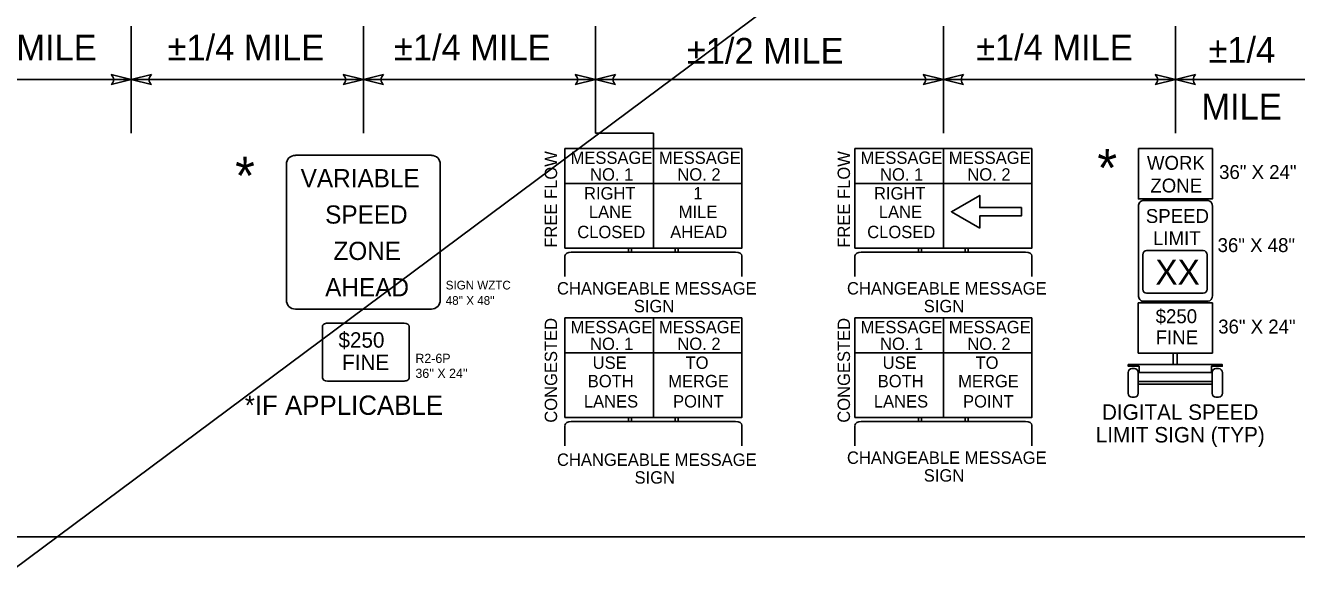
# Model space of a CAD drawing. Extents: x 1379436 to 1387057, y 792703 to 795604.
# Drawn here: x 1381631 to 1382289, y 794247 to 794533 of the extents above; entities that cross this region are included whole.
import ezdxf

# ---------------------------------------------------------------- set-up
doc = ezdxf.new("R2010")
doc.units = 0
for name, color, linetype in [('Default', 7, 'Continuous'), ('DEV CMS TEXT CELL', 7, 'Continuous'), ('DEV LINE TERMINATOR TYPE 3 CELL', 7, 'Continuous'), ('Gray Area Fill Shapes', 7, 'Continuous'), ('Old_Level_2', 7, 'Continuous'), ('RS R5-1A CELL', 7, 'Continuous'), ('TCP Linework', 7, 'Continuous'), ('Text', 7, 'Continuous'), ('WS W24-1cP24 CELL', 7, 'Continuous')]:
    doc.layers.add(name, color=color, linetype=linetype)

msp = doc.modelspace()

# ---------------------------------------------------------------- linework, layer by layer
at = {"layer": 'Default'}
for p, q in [((1379547.85, 792703.35), (1383441.11, 795604.31)), ((1381685.89, 794532.28), (1381685.89, 794476.77)), ((1381805.89, 794532.28), (1381805.89, 794476.77)), ((1381925.89, 794532.28), (1381925.89, 794476.77)), ((1382105.89, 794532.28), (1382105.89, 794476.77)), ((1382225.89, 794532.28), (1382225.89, 794476.77)), ((1380845.89, 794504.52), (1382495.75, 794504.52)), ((1381925.89, 794476.77), (1381925.89, 794504.52)), ((1381925.89, 794476.77), (1381955.91, 794476.77)), ((1381955.91, 794468.84), (1381955.91, 794476.77)), ((1380316.98, 794267.83), (1382566.98, 794267.84))]:
    msp.add_line(p, q, dxfattribs=at)
for points in [[(1382206.77, 794392.85), (1382206.77, 794438.89)], [(1382209, 794441.93), (1382242.78, 794441.93)], [(1382245.01, 794438.89), (1382245.01, 794392.85)], [(1382242.78, 794389.81), (1382209, 794389.81)]]:
    msp.add_lwpolyline(points, dxfattribs=at)
for centre, major_axis, start_param, end_param in [((1382209, 794438.89), (0, 3.04), 6.282958, 7.853982), ((1382242.78, 794438.89), (0, 3.04), 4.712389, 6.283185), ((1382209, 794392.85), (0, 3.04), 1.570796, 3.141593), ((1382242.78, 794392.85), (0, -3.04), 0, 1.570796)]:
    msp.add_ellipse(centre, major_axis=major_axis, ratio=0.733811, start_param=start_param, end_param=end_param, dxfattribs=at)
at = {"layer": 'DEV CMS TEXT CELL'}
for p, q in [((1381910.16, 794468.84), (1382001.67, 794468.84)), ((1381910.16, 794417.37), (1381910.16, 794468.84)), ((1381955.91, 794417.37), (1381955.91, 794468.84)), ((1381955.91, 794417.37), (1381955.91, 794468.84)), ((1382001.67, 794417.37), (1382001.67, 794468.84)), ((1382060.13, 794468.84), (1382151.65, 794468.84)), ((1382060.13, 794417.37), (1382060.13, 794468.84)), ((1382105.89, 794417.37), (1382105.89, 794468.84)), ((1382105.89, 794417.37), (1382105.89, 794468.84)), ((1382151.65, 794417.37), (1382151.65, 794468.84)), ((1381910.16, 794450.73), (1381955.91, 794450.73)), ((1382001.67, 794450.73), (1381955.91, 794450.73)), ((1382060.13, 794450.73), (1382105.89, 794450.73)), ((1382151.65, 794450.73), (1382105.89, 794450.73)), ((1382001.67, 794417.37), (1381910.16, 794417.37)), ((1381943.05, 794417.37), (1381943.05, 794415.24)), ((1381944.63, 794417.37), (1381944.63, 794415.24)), ((1381967.2, 794417.37), (1381967.2, 794415.24)), ((1381968.78, 794417.37), (1381968.78, 794415.24)), ((1382151.65, 794417.37), (1382060.13, 794417.37)), ((1382093.02, 794417.37), (1382093.02, 794415.24)), ((1382094.61, 794417.37), (1382094.61, 794415.24)), ((1382117.17, 794417.37), (1382117.17, 794415.24)), ((1382118.75, 794417.37), (1382118.75, 794415.24)), ((1381910.16, 794413.24), (1381910.16, 794402.62)), ((1381913.36, 794415.24), (1381998.45, 794415.24)), ((1382001.69, 794413.25), (1382001.69, 794402.63)), ((1382060.13, 794413.24), (1382060.13, 794402.62)), ((1382063.34, 794415.24), (1382148.42, 794415.24)), ((1382151.66, 794413.25), (1382151.66, 794402.63)), ((1381910.16, 794381.18), (1382001.67, 794381.18)), ((1381910.16, 794329.7), (1381910.16, 794381.18)), ((1381955.91, 794329.7), (1381955.91, 794381.18)), ((1381955.91, 794329.7), (1381955.91, 794381.18)), ((1382001.67, 794329.7), (1382001.67, 794381.18)), ((1382060.13, 794381.18), (1382151.65, 794381.18)), ((1382060.13, 794329.7), (1382060.13, 794381.18)), ((1382105.89, 794329.7), (1382105.89, 794381.18)), ((1382105.89, 794329.7), (1382105.89, 794381.18)), ((1382151.65, 794329.7), (1382151.65, 794381.18)), ((1381910.16, 794363.07), (1381955.91, 794363.07)), ((1382001.67, 794363.07), (1381955.91, 794363.07)), ((1382060.13, 794363.07), (1382105.89, 794363.07)), ((1382151.65, 794363.07), (1382105.89, 794363.07)), ((1382001.67, 794329.7), (1381910.16, 794329.7)), ((1381910.16, 794325.57), (1381910.16, 794314.95)), ((1381913.36, 794327.57), (1381998.45, 794327.57)), ((1381943.05, 794329.7), (1381943.05, 794327.57)), ((1381944.63, 794329.7), (1381944.63, 794327.57)), ((1381967.2, 794329.7), (1381967.2, 794327.57)), ((1381968.78, 794329.7), (1381968.78, 794327.57)), ((1382001.69, 794325.59), (1382001.69, 794314.97)), ((1382151.65, 794329.7), (1382060.13, 794329.7)), ((1382060.13, 794325.57), (1382060.13, 794314.95)), ((1382063.34, 794327.57), (1382148.42, 794327.57)), ((1382093.02, 794329.7), (1382093.02, 794327.57)), ((1382094.61, 794329.7), (1382094.61, 794327.57)), ((1382117.17, 794329.7), (1382117.17, 794327.57)), ((1382118.75, 794329.7), (1382118.75, 794327.57)), ((1382151.66, 794325.59), (1382151.66, 794314.97))]:
    msp.add_line(p, q, dxfattribs=at)
msp.add_lwpolyline([(1382124.71, 794427.67), (1382110.03, 794436.15), (1382124.71, 794444.63), (1382124.71, 794438.28), (1382146.22, 794438.28), (1382146.22, 794434.02), (1382124.71, 794434.02)], close=True, dxfattribs=at)
for centre, major_axis, start_param, end_param in [((1381913.38, 794413.25), (-3.24, 0), 4.712389, 6.283185), ((1381998.45, 794413.25), (3.24, 0), 0, 1.570796), ((1382063.35, 794413.25), (-3.24, 0), 4.712389, 6.283185), ((1382148.42, 794413.25), (3.24, 0), 0, 1.570796), ((1381913.38, 794325.59), (-3.24, 0), 4.712389, 6.283185), ((1381998.45, 794325.59), (3.24, 0), 0, 1.570796), ((1382063.35, 794325.59), (-3.24, 0), 4.712389, 6.283185), ((1382148.42, 794325.59), (3.24, 0), 0, 1.570796)]:
    msp.add_ellipse(centre, major_axis=major_axis, ratio=0.606795, start_param=start_param, end_param=end_param, dxfattribs=at)
at = {"layer": 'DEV LINE TERMINATOR TYPE 3 CELL'}
for points in [[(1381675.49, 794501.92), (1381685.89, 794504.52), (1381675.49, 794507.12)], [(1381675.49, 794501.92), (1381685.89, 794504.52), (1381675.49, 794507.12)], [(1381696.28, 794501.92), (1381685.89, 794504.52), (1381696.28, 794507.12)], [(1381696.28, 794501.92), (1381685.89, 794504.52), (1381696.28, 794507.12)], [(1381795.49, 794501.92), (1381805.89, 794504.52), (1381795.49, 794507.12)], [(1381795.49, 794501.92), (1381805.89, 794504.52), (1381795.49, 794507.12)], [(1381816.28, 794501.92), (1381805.89, 794504.52), (1381816.28, 794507.12)], [(1381816.28, 794501.92), (1381805.89, 794504.52), (1381816.28, 794507.12)], [(1381915.49, 794501.92), (1381925.89, 794504.52), (1381915.49, 794507.12)], [(1381915.49, 794501.92), (1381925.89, 794504.52), (1381915.49, 794507.12)], [(1381936.28, 794501.92), (1381925.89, 794504.52), (1381936.28, 794507.12)], [(1381936.28, 794501.92), (1381925.89, 794504.52), (1381936.28, 794507.12)], [(1382095.49, 794501.92), (1382105.89, 794504.52), (1382095.49, 794507.12)], [(1382095.49, 794501.92), (1382105.89, 794504.52), (1382095.49, 794507.12)], [(1382116.28, 794501.92), (1382105.89, 794504.52), (1382116.28, 794507.12)], [(1382116.28, 794501.92), (1382105.89, 794504.52), (1382116.28, 794507.12)], [(1382215.49, 794501.92), (1382225.89, 794504.52), (1382215.49, 794507.12)], [(1382215.49, 794501.92), (1382225.89, 794504.52), (1382215.49, 794507.12)], [(1382236.28, 794501.92), (1382225.89, 794504.52), (1382236.28, 794507.12)], [(1382236.28, 794501.92), (1382225.89, 794504.52), (1382236.28, 794507.12)]]:
    msp.add_lwpolyline(points, dxfattribs=at)
for centre, start, end in [((1381673.21, 794504.52), 311.32644, 48.67357), ((1381673.21, 794504.52), 311.32644, 48.67357), ((1381698.57, 794504.52), 131.32643, 228.67356), ((1381698.57, 794504.52), 131.32643, 228.67356), ((1381793.21, 794504.52), 311.32644, 48.67357), ((1381793.21, 794504.52), 311.32644, 48.67357), ((1381818.57, 794504.52), 131.32643, 228.67356), ((1381818.57, 794504.52), 131.32643, 228.67356), ((1381913.21, 794504.52), 311.32644, 48.67357), ((1381913.21, 794504.52), 311.32644, 48.67357), ((1381938.57, 794504.52), 131.32643, 228.67356), ((1381938.57, 794504.52), 131.32643, 228.67356), ((1382093.21, 794504.52), 311.32644, 48.67357), ((1382093.21, 794504.52), 311.32644, 48.67357), ((1382118.57, 794504.52), 131.32643, 228.67356), ((1382118.57, 794504.52), 131.32643, 228.67356), ((1382213.21, 794504.52), 311.32644, 48.67357), ((1382213.21, 794504.52), 311.32644, 48.67357), ((1382238.57, 794504.52), 131.32643, 228.67356), ((1382238.57, 794504.52), 131.32643, 228.67356)]:
    msp.add_arc(centre, 3.46, start, end, dxfattribs=at)
at = {"layer": 'Gray Area Fill Shapes'}
for p, q in [((1382209.03, 794413.85), (1382209.03, 794396.09)), ((1382240.3, 794416.01), (1382211.01, 794416.01)), ((1382242.28, 794396.09), (1382242.28, 794413.85)), ((1382211.01, 794393.93), (1382240.3, 794393.93))]:
    msp.add_line(p, q, dxfattribs=at)
for points in [[(1381955.91, 794450.73), (1381910.16, 794450.73), (1381910.16, 794417.37), (1381955.91, 794417.37)], [(1381955.91, 794450.73), (1382001.67, 794450.73), (1382001.67, 794417.37), (1381955.91, 794417.37)], [(1382105.89, 794450.73), (1382060.13, 794450.73), (1382060.13, 794417.37), (1382105.89, 794417.37)], [(1382105.89, 794450.73), (1382151.65, 794450.73), (1382151.65, 794417.37), (1382105.89, 794417.37)], [(1381955.91, 794363.07), (1381910.16, 794363.07), (1381910.16, 794329.7), (1381955.91, 794329.7)], [(1381955.91, 794363.07), (1382001.67, 794363.07), (1382001.67, 794329.7), (1381955.91, 794329.7)], [(1382105.89, 794363.07), (1382060.13, 794363.07), (1382060.13, 794329.7), (1382105.89, 794329.7)], [(1382105.89, 794363.07), (1382151.65, 794363.07), (1382151.65, 794329.7), (1382105.89, 794329.7)]]:
    msp.add_lwpolyline(points, close=True, dxfattribs=at)
for centre, major_axis, start_param, end_param in [((1382211.01, 794413.85), (0, 2.16), 0, 1.570796), ((1382240.3, 794413.85), (0, 2.16), 4.712389, 6.283185), ((1382211.01, 794396.09), (0, -2.16), 4.712389, 6.283185), ((1382240.3, 794396.09), (0, -2.16), 0, 1.570796)]:
    msp.add_ellipse(centre, major_axis=major_axis, ratio=0.917264, start_param=start_param, end_param=end_param, dxfattribs=at)
at = {"layer": 'Old_Level_2'}
for points in [[(1382206.74, 794468.84), (1382245.04, 794468.84), (1382245.04, 794442.79), (1382206.74, 794442.79)], [(1382206.72, 794388.92), (1382245.01, 794388.92), (1382245.01, 794362.98), (1382206.72, 794362.98)]]:
    msp.add_lwpolyline(points, close=True, dxfattribs=at)
at = {"layer": 'RS R5-1A CELL'}
msp.add_line((1381827.02, 794348.5), (1381787.34, 794348.5), dxfattribs=at)
for points in [[(1381787.34, 794378.45), (1381827.02, 794378.45)], [(1381787.34, 794378.45), (1381807.18, 794378.45)], [(1381807.18, 794378.45), (1381827.02, 794378.45)], [(1381784.72, 794350.25), (1381784.72, 794376.7)], [(1381784.72, 794350.25), (1381784.72, 794376.7)], [(1381829.64, 794376.7), (1381829.64, 794350.25)], [(1381829.64, 794376.7), (1381829.64, 794350.25)], [(1381807.18, 794348.5), (1381787.34, 794348.5)], [(1381827.02, 794348.5), (1381807.18, 794348.5)]]:
    msp.add_lwpolyline(points, dxfattribs=at)
for centre, major_axis, start_param, end_param in [((1381787.34, 794376.7), (-2.62, 0), 4.712162, 6.283185), ((1381787.34, 794376.7), (-2.62, 0), 4.712162, 6.283185), ((1381827.02, 794376.7), (2.62, 0), 0, 1.570796), ((1381827.02, 794376.7), (2.62, 0), 0, 1.570796), ((1381787.34, 794350.25), (-2.62, 0), 0, 1.570796), ((1381787.34, 794350.25), (-2.62, 0), 0, 1.570796), ((1381827.02, 794350.25), (-2.62, 0), 1.570796, 3.141593), ((1381827.02, 794350.25), (-2.62, 0), 1.570796, 3.141593)]:
    msp.add_ellipse(centre, major_axis=major_axis, ratio=0.666667, start_param=start_param, end_param=end_param, dxfattribs=at)
at = {"layer": 'TCP Linework'}
for points in [[(1382224.73, 794357), (1382226.86, 794357), (1382226.86, 794362.98), (1382224.73, 794362.98)], [(1382206.67, 794346.92), (1382244.93, 794346.92), (1382244.93, 794348.19), (1382206.67, 794348.19)]]:
    msp.add_lwpolyline(points, close=True, dxfattribs=at)
for points in [[(1382201.43, 794342.23), (1382201.43, 794352.88)], [(1382244.91, 794357), (1382206.68, 794357), (1382201.5, 794356.99), (1382201.5, 794356.15), (1382207.07, 794356.16), (1382207.07, 794352.9), (1382244.51, 794352.93), (1382244.51, 794356.15)], [(1382203.34, 794354.96), (1382204.77, 794354.96)], [(1382206.67, 794352.88), (1382206.67, 794342.23)], [(1382206.68, 794357), (1382244.91, 794357), (1382250.09, 794356.99), (1382250.09, 794356.15), (1382244.51, 794356.17), (1382244.51, 794352.87), (1382207.07, 794352.9), (1382207.07, 794356.15)], [(1382244.93, 794342.23), (1382244.93, 794352.88)], [(1382246.83, 794354.96), (1382248.27, 794354.96)], [(1382250.17, 794352.88), (1382250.17, 794342.23)], [(1382204.77, 794340.15), (1382203.34, 794340.15)], [(1382248.27, 794340.15), (1382246.83, 794340.15)]]:
    msp.add_lwpolyline(points, dxfattribs=at)
for centre, major_axis, start_param, end_param in [((1382203.34, 794352.88), (0, 2.08), 0, 1.570796), ((1382204.77, 794352.88), (0, 2.08), 4.712389, 6.283185), ((1382246.83, 794352.88), (0, -2.08), 3.141593, 4.712389), ((1382248.27, 794352.88), (0, 2.08), 4.712389, 6.283185), ((1382203.34, 794342.23), (0, -2.08), 4.712389, 6.283185), ((1382204.77, 794342.23), (0, -2.08), 0, 1.570796), ((1382246.83, 794342.23), (0, -2.08), 4.712389, 6.283185), ((1382248.27, 794342.23), (0, 2.08), 3.141593, 4.712389)]:
    msp.add_ellipse(centre, major_axis=major_axis, ratio=0.917264, start_param=start_param, end_param=end_param, dxfattribs=at)
at = {"layer": 'WS W24-1cP24 CELL'}
msp.add_line((1381845.7, 794460.7), (1381845.7, 794390.39), dxfattribs=at)
for points in [[(1381770.72, 794465.34), (1381841.06, 794465.34)], [(1381766.07, 794390.39), (1381766.07, 794460.7)], [(1381805.89, 794385.75), (1381770.72, 794385.75)], [(1381841.06, 794385.75), (1381805.89, 794385.75)]]:
    msp.add_lwpolyline(points, dxfattribs=at)
for centre, major_axis, start_param, end_param in [((1381770.72, 794460.7), (-4.64, 0), 4.712162, 6.283185), ((1381841.06, 794460.7), (4.64, 0), 0, 1.570796), ((1381770.72, 794390.39), (-4.64, 0), 0, 1.570796), ((1381841.06, 794390.39), (-4.64, 0), 1.570796, 3.141593)]:
    msp.add_ellipse(centre, major_axis=major_axis, ratio=0.999525, start_param=start_param, end_param=end_param, dxfattribs=at)

# ---------------------------------------------------------------- texts
at = {"layer": 'Default'}
for s, height, p in [('*', 19.68, (1381739.56, 794444.97)), ('*', 19.68, (1382185.49, 794449.01)), ('36" X 24"', 7.203, (1382248.49, 794453.1)), ('36" X 48"', 7.203, (1382247.72, 794415.26)), ('36" X 24"', 7.203, (1382248.02, 794373.11)), ('*IF APPLICABLE', 10, (1381744.57, 794331.01))]:
    msp.add_text(s, height=height, dxfattribs=at).set_placement(p)
at = {"layer": 'DEV CMS TEXT CELL'}
for s, rotation, p in [('FREE FLOW', 90, (1381906.1, 794417.55)), ('MESSAGE', 360, (1381958.72, 794460.92)), ('FREE FLOW', 90, (1382057.6, 794417.55)), ('MESSAGE', 360, (1382108.69, 794460.92)), ('NO. 2', 360, (1381968.29, 794452.25)), ('NO. 2', 360, (1382118.27, 794452.25)), ('CONGESTED', 90, (1381906.1, 794326.94)), ('MESSAGE', 360, (1381958.72, 794373.25)), ('CONGESTED', 90, (1382057.6, 794326.94)), ('MESSAGE', 360, (1382108.69, 794373.25)), ('NO. 2', 360, (1381968.29, 794364.58)), ('NO. 2', 360, (1382118.27, 794364.58))]:
    msp.add_text(s, height=6.403, rotation=rotation, dxfattribs=at).set_placement(p)
for s, height, p in [('MESSAGE', 6.403, (1381913.05, 794460.92)), ('MESSAGE', 6.403, (1382063.02, 794460.92)), ('NO. 1', 6.403, (1381923.16, 794452.25)), ('NO. 1', 6.403, (1382073.14, 794452.25)), ('RIGHT', 6.403, (1381920.03, 794442.49)), ('1', 6.4, (1381976.53, 794442.49)), ('RIGHT', 6.403, (1382070.01, 794442.49)), ('LANE', 6.403, (1381922.53, 794432.95)), ('MILE', 6.403, (1381969.02, 794432.95)), ('LANE', 6.403, (1382072.5, 794432.95)), ('CLOSED', 6.403, (1381916.53, 794422.47)), ('AHEAD', 6.403, (1381964.61, 794422.47)), ('CLOSED', 6.403, (1382066.5, 794422.47)), ('CHANGEABLE MESSAGE', 6.4025, (1381906.04, 794393.3)), ('CHANGEABLE MESSAGE', 6.4025, (1382056.02, 794393.3)), ('SIGN', 6.403, (1381945.78, 794384.11)), ('SIGN', 6.403, (1382095.75, 794384.11)), ('MESSAGE', 6.403, (1381913.05, 794373.25)), ('MESSAGE', 6.403, (1382063.02, 794373.25)), ('NO. 1', 6.403, (1381923.16, 794364.58)), ('NO. 1', 6.403, (1382073.14, 794364.58)), ('USE', 6.403, (1381924.5, 794354.82)), ('TO', 6.403, (1381972.54, 794354.82)), ('USE', 6.403, (1382074.47, 794354.82)), ('TO', 6.403, (1382122.52, 794354.82)), ('BOTH', 6.403, (1381921.96, 794345.28)), ('MERGE', 6.403, (1381963.54, 794345.28)), ('BOTH', 6.403, (1382071.93, 794345.28)), ('MERGE', 6.403, (1382113.52, 794345.28)), ('LANES', 6.403, (1381919.94, 794334.8)), ('POINT', 6.403, (1381966.07, 794334.8)), ('LANES', 6.403, (1382069.92, 794334.8)), ('POINT', 6.403, (1382116.05, 794334.8)), ('CHANGEABLE MESSAGE', 6.4025, (1381906.04, 794304.6)), ('CHANGEABLE MESSAGE', 6.4025, (1382056.02, 794305.64)), ('SIGN', 6.403, (1381946.16, 794295.41)), ('SIGN', 6.403, (1382095.75, 794296.45))]:
    msp.add_text(s, height=height, dxfattribs=at).set_placement(p)
at = {"layer": 'RS R5-1A CELL'}
for s, height, p in [('$250', 7.986, (1381793.04, 794365.77)), ('FINE', 7.986, (1381794.92, 794354.15)), ('R2-6P', 4.792, (1381832.83, 794357.85)), ("36'' X 24''", 4.7916, (1381832.83, 794350.11))]:
    msp.add_text(s, height=height, dxfattribs=at).set_placement(p)
at = {"layer": 'Text'}
for s, height, p in [('±1/4 MILE', 13.31, (1381586.96, 794514.45)), ('±1/4 MILE', 13.31, (1381704.63, 794514.45)), ('±1/4 MILE', 13.31, (1381821.75, 794514.45)), ('±1/2 MILE', 13.31, (1381973.23, 794512.79)), ('±1/4 MILE', 13.31, (1382122.82, 794514.45)), ('±1/4', 13.31, (1382242.99, 794513.29)), ('MILE', 13.31, (1382239.36, 794483.88)), ('WORK', 7.203, (1382211.16, 794457.85)), ('ZONE', 7.203, (1382212.93, 794446.1)), ('XX', 12.879, (1382215.53, 794398.43)), ('$250', 7.203, (1382215.68, 794378.46)), ('FINE', 7.203, (1382215.68, 794367.5)), ('DIGITAL SPEED', 8.0031, (1382187.91, 794328.43)), ('LIMIT SIGN (TYP)', 8.0031, (1382184.7, 794316.7))]:
    msp.add_text(s, height=height, dxfattribs=at).set_placement(p)
for s, p in [('SPEED', (1382210.6, 794430.33)), ('LIMIT', (1382214.31, 794418.84))]:
    msp.add_text(s, height=7.203, rotation=360, dxfattribs=at).set_placement(p)
at = {"layer": 'WS W24-1cP24 CELL'}
for s, height, p in [('VARIABLE', 9.411, (1381773.48, 794448.82)), ('SPEED', 9.411, (1381786.14, 794430)), ('ZONE', 9.411, (1381790.42, 794411.18)), ('AHEAD', 9.411, (1381786.14, 794392.35)), ('SIGN WZTC', 4.481, (1381848.52, 794395.91)), ("48'' X 48''", 4.4813, (1381848.52, 794387.97))]:
    msp.add_text(s, height=height, rotation=360, dxfattribs=at).set_placement(p)

doc.saveas('drawing.dxf')
